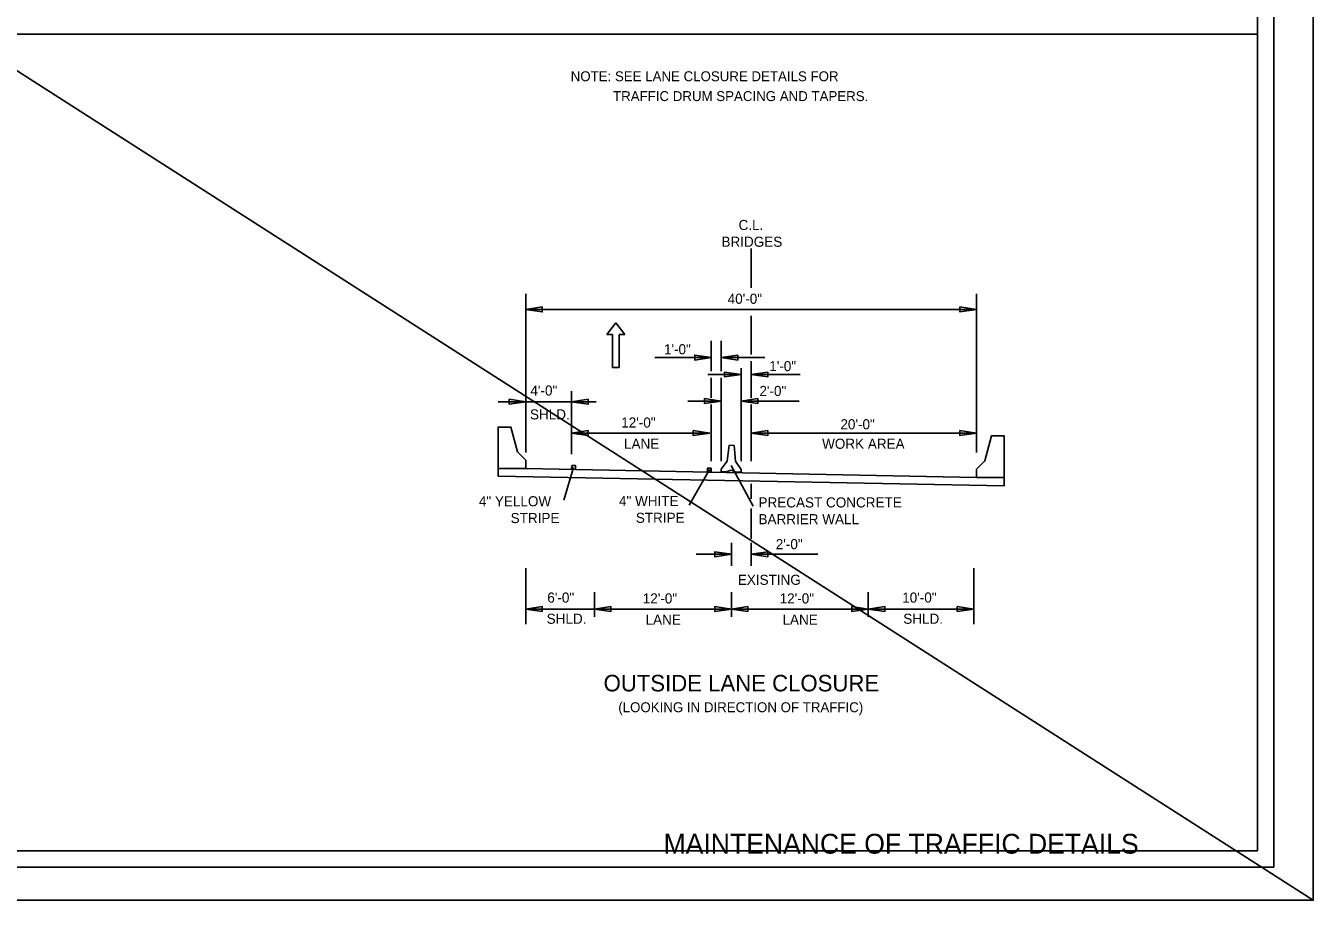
# Model space of a CAD drawing. Extents: x 13528 to 25043, y 7635 to 10612.
# Drawn here: x 22655 to 23433, y 9545 to 10073 of the extents above; entities that cross this region are included whole.
import ezdxf

# ---------------------------------------------------------------- set-up
doc = ezdxf.new("R2010")
doc.units = 0
for name, color, linetype in [('Default', 7, 'Continuous'), ('R_Border Plan-Plan', 7, 'Continuous'), ('R_Draft', 7, 'Continuous'), ('R_Revision Date Text', 7, 'Continuous'), ('STAMP_PE_TAEGTMEYER-SIGNATURE', 7, 'Continuous'), ('STAMP_PRELIMINARY', 7, 'Continuous')]:
    doc.layers.add(name, color=color, linetype=linetype)

msp = doc.modelspace()

# ---------------------------------------------------------------- linework, layer by layer
at = {"layer": 'Default'}
for p, q in [((21766.57, 10611.55), (23433.27, 9544.86)), ((23093.63, 9914.99), (23093.63, 9938.83)), ((22957.42, 9815.5), (22957.42, 9911.32)), ((23229.77, 9815.5), (23229.77, 9911.32)), ((23229.77, 9902), (22957.42, 9902)), ((23093.63, 9874.65), (23093.63, 9898.1)), ((23069.51, 9882.98), (23069.51, 9864.55)), ((23075.54, 9882.98), (23075.54, 9864.55)), ((23069.51, 9872.82), (23035.35, 9872.82)), ((23101.91, 9872.82), (23075.54, 9872.82)), ((23087.6, 9866.36), (23087.6, 9858.89)), ((23093.63, 9848.53), (23093.63, 9870.65)), ((23087.6, 9862.63), (23067.44, 9862.63)), ((23069.51, 9860.55), (23069.51, 9848.45)), ((23075.54, 9860.55), (23075.54, 9810.19)), ((23087.6, 9858.89), (23087.6, 9810.19)), ((23123.21, 9862.63), (23093.63, 9862.63)), ((22985.15, 9814.48), (22985.15, 9852.65)), ((22999.93, 9846.19), (22940.69, 9846.19)), ((23075.54, 9846.53), (23055.37, 9846.53)), ((23069.51, 9844.45), (23069.51, 9834.76)), ((23122.63, 9846.53), (23087.6, 9846.53)), ((23093.63, 9810.19), (23093.63, 9844.53)), ((23069.51, 9834.76), (23069.51, 9810.19)), ((22985.93, 9827.19), (23068.66, 9827.19)), ((23093.63, 9827.19), (23229.77, 9827.19)), ((22980.49, 9786.58), (22986.3, 9806.49)), ((22985.15, 9805.34), (22985.19, 9807.63)), ((22985.19, 9807.63), (22985.15, 9805.34)), ((22985.15, 9805.34), (22987.44, 9805.3)), ((22985.19, 9807.63), (22987.49, 9807.59)), ((22987.49, 9807.59), (22985.19, 9807.63)), ((22987.49, 9807.59), (22987.44, 9805.3)), ((22987.44, 9805.3), (22987.49, 9807.59)), ((23056.13, 9783.57), (23068.36, 9804.81)), ((23067.21, 9805.95), (23067.21, 9803.66)), ((23069.51, 9805.95), (23067.21, 9805.95)), ((23067.21, 9805.95), (23067.21, 9803.66)), ((23069.51, 9804.81), (23067.21, 9804.81)), ((23067.21, 9803.66), (23069.51, 9803.66)), ((23069.51, 9803.66), (23069.51, 9805.95)), ((23069.51, 9803.66), (23069.51, 9805.95)), ((23094.91, 9783.01), (23081.48, 9807.7)), ((23093.63, 9787.53), (23093.63, 9796.62)), ((23093.63, 9763.31), (23093.63, 9781.62)), ((23081.67, 9747.07), (23081.67, 9760.82)), ((23093.63, 9747.07), (23093.63, 9760.82)), ((23060.32, 9753.94), (23081.67, 9753.94)), ((23093.63, 9753.94), (23133.96, 9753.94)), ((22957.42, 9745.64), (22957.42, 9711.77)), ((23228.18, 9745.64), (23228.18, 9711.77)), ((22957.42, 9731.05), (22957.42, 9716.09)), ((22998.93, 9731.05), (22998.93, 9716.09)), ((23081.67, 9731.05), (23081.67, 9716.09)), ((23164.41, 9731.05), (23164.41, 9716.09)), ((22957.42, 9720.89), (22998.93, 9720.89)), ((23081.67, 9720.89), (22998.93, 9720.89)), ((23164.41, 9720.89), (23081.67, 9720.89)), ((23164.41, 9720.89), (23228.18, 9720.89))]:
    msp.add_line(p, q, dxfattribs=at)
for points in [[(22957.42, 9902), (22967.42, 9903.5), (22967.42, 9900.5)], [(23229.77, 9902), (23219.77, 9903.5), (23219.77, 9900.5)], [(23069.51, 9872.82), (23059.51, 9874.32), (23059.51, 9871.32)], [(23075.54, 9872.82), (23085.54, 9874.32), (23085.54, 9871.32)], [(23087.6, 9862.63), (23077.6, 9864.13), (23077.6, 9861.13)], [(23093.63, 9862.63), (23103.63, 9864.13), (23103.63, 9861.13)], [(22957.42, 9846.19), (22947.42, 9847.69), (22947.42, 9844.69)], [(22985.15, 9846.19), (22995.15, 9847.69), (22995.15, 9844.69)], [(23075.54, 9846.53), (23065.54, 9848.03), (23065.54, 9845.03)], [(23087.6, 9846.53), (23097.6, 9848.03), (23097.6, 9845.03)], [(22985.15, 9827.19), (22995.15, 9828.69), (22995.15, 9825.69)], [(23068.66, 9827.19), (23058.66, 9828.69), (23058.66, 9825.69)], [(23093.63, 9827.19), (23103.63, 9828.69), (23103.63, 9825.69)], [(23229.77, 9827.19), (23219.77, 9828.69), (23219.77, 9825.69)], [(23081.67, 9753.94), (23071.67, 9755.44), (23071.67, 9752.44)], [(23093.63, 9753.94), (23103.63, 9755.44), (23103.63, 9752.44)], [(22957.42, 9720.89), (22967.42, 9722.39), (22967.42, 9719.39)], [(22998.93, 9720.89), (23008.93, 9722.39), (23008.93, 9719.39)], [(23081.67, 9720.89), (23071.67, 9722.39), (23071.67, 9719.39)], [(23081.67, 9720.89), (23091.67, 9722.39), (23091.67, 9719.39)], [(23164.41, 9720.89), (23154.41, 9722.39), (23154.41, 9719.39)], [(23164.41, 9720.89), (23174.41, 9722.39), (23174.41, 9719.39)], [(23228.18, 9720.89), (23218.18, 9722.39), (23218.18, 9719.39)]]:
    msp.add_lwpolyline(points, close=True, dxfattribs=at)
at = {"layer": 'R_Draft'}
for q in [(23409.51, 10592.07), (21828.61, 9564.77)]:
    msp.add_line((23409.51, 9564.77), q, dxfattribs=at)
at = {"layer": 'R_Revision Date Text'}
for points in [[(21766.57, 10611.55), (23433.27, 10611.55), (23433.27, 9544.86), (21766.57, 9544.86)], [(21838.61, 10582.07), (23086.31, 10582.07), (23086.31, 10532.67), (23174.01, 10532.67), (23294.51, 10532.67), (23294.51, 10421.01), (23399.51, 10421.01), (23399.51, 9574.77), (21838.61, 9574.77)], [(21838.61, 10068.42), (23399.51, 10068.42), (23399.51, 9574.77), (21838.61, 9574.77)]]:
    msp.add_lwpolyline(points, close=True, dxfattribs=at)
at = {"layer": 'STAMP_PE_TAEGTMEYER-SIGNATURE'}
for p, q in [((23006.49, 9886.76), (23011.91, 9893.8)), ((23011.91, 9893.8), (23017.34, 9886.76)), ((23006.49, 9886.76), (23009.88, 9886.76)), ((23009.88, 9886.76), (23009.88, 9866.82)), ((23013.95, 9886.76), (23013.95, 9866.82)), ((23013.95, 9886.76), (23017.34, 9886.76)), ((23009.88, 9866.82), (23013.95, 9866.82))]:
    msp.add_line(p, q, dxfattribs=at)
at = {"layer": 'STAMP_PRELIMINARY'}
for p, q in [((23079.21, 9810.32), (23080.4, 9819.85)), ((23080.4, 9819.85), (23083.42, 9819.79)), ((23083.42, 9819.79), (23084.23, 9810.22)), ((23075.59, 9805.37), (23079.21, 9810.32)), ((23084.23, 9810.22), (23087.65, 9805.12)), ((22940.67, 9805.89), (22940.67, 9801.23)), ((22957.46, 9805.89), (22940.67, 9805.89)), ((23229.81, 9800.47), (22957.46, 9805.89)), ((23075.57, 9803.86), (23075.59, 9805.37)), ((23078.59, 9803.8), (23075.57, 9803.86)), ((23081.62, 9804.74), (23078.59, 9803.8)), ((23084.62, 9803.68), (23081.62, 9804.74)), ((23087.63, 9803.62), (23084.62, 9803.68)), ((23087.65, 9805.12), (23087.63, 9803.62)), ((23246.56, 9795.27), (22940.67, 9801.23)), ((23229.82, 9800.47), (23246.6, 9800.47)), ((23246.59, 9800.46), (23246.59, 9795.27))]:
    msp.add_line(p, q, dxfattribs=at)
for points in [[(22940.67, 9805.89), (22940.67, 9830.89), (22948.5, 9830.89), (22952.47, 9815.89)], [(23246.6, 9800.46), (23246.6, 9825.46), (23238.78, 9825.46), (23234.81, 9810.46)], [(22952.47, 9815.89), (22957.47, 9810.89), (22957.46, 9805.89)], [(23234.81, 9810.46), (23229.81, 9805.46), (23229.82, 9800.47)]]:
    msp.add_lwpolyline(points, dxfattribs=at)

# ---------------------------------------------------------------- texts
at = {"layer": 'Default'}
for s, height, p in [('NOTE: SEE LANE CLOSURE DETAILS FOR ', 6, (22984.59, 10039.89)), (' TRAFFIC DRUM SPACING AND TAPERS.', 6, (23007.95, 10027.89)), ('C.L.', 6.1, (23086.04, 9949.95)), (' BRIDGES', 6.1, (23073.44, 9939.82)), ('40\'-0"', 6.1, (23079.45, 9905.36)), ('1\'-0"', 6.1, (23040.93, 9874.85)), ('1\'-0"', 6.1, (23104.56, 9864.66)), ('4\'-0"', 6.1, (22960.26, 9849.88)), ('2\'-0"', 6.1, (23098.62, 9849.63)), ('SHLD.', 6.1, (22960, 9835.49)), ('12\'-0"', 6.1, (23015.12, 9830.55)), ('20\'-0"', 6.1, (23147.56, 9829.5)), ('LANE', 6.1, (23016.82, 9817.72)), ('WORK AREA', 6.1, (23136.51, 9817.72)), ('4" YELLOW', 6.1, (22929.11, 9782.96)), ('4" WHITE', 6.1, (23013.78, 9783.11)), ('PRECAST CONCRETE', 6.1, (23098.07, 9782.26)), ('STRIPE', 6.1, (22948.33, 9772.83)), ('STRIPE', 6.1, (23023.96, 9772.98)), ('BARRIER WALL', 6.1, (23098.07, 9772.13)), ('2\'-0"', 6.1, (23108.52, 9757.05)), ('EXISTING', 6.1, (23085.58, 9735.5)), ('6\'-0"', 6.1, (22970.46, 9724.76)), ('12\'-0"', 6.1, (23028.12, 9724.25)), ('12\'-0"', 6.1, (23110.86, 9724.25)), ('10\'-0"', 6.1, (23184.91, 9724.76)), ('SHLD.', 6.1, (22970.09, 9711.96)), ('LANE', 6.1, (23029.83, 9711.43)), ('LANE', 6.1, (23112.56, 9711.43)), ('SHLD.', 6.1, (23185.55, 9711.96)), ('OUTSIDE LANE CLOSURE', 10.002, (23004.48, 9671.09)), ('(LOOKING IN DIRECTION OF TRAFFIC)', 6, (23013.36, 9658.52))]:
    msp.add_text(s, height=height, dxfattribs=at).set_placement(p)
at = {"layer": 'R_Border Plan-Plan'}
msp.add_text('MAINTENANCE OF TRAFFIC DETAILS', height=12, dxfattribs=at).set_placement((23040.71, 9573.02))

doc.saveas('drawing.dxf')
